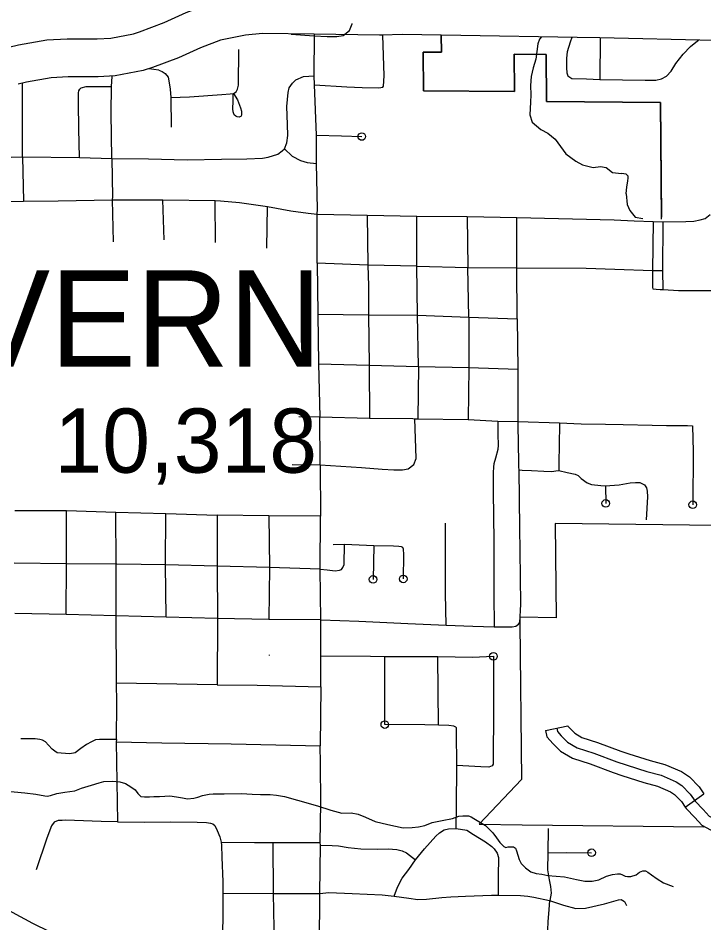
# Model space of a CAD drawing. Extents: x 22866 to 28196, y 1324810 to 1328105.
# Drawn here: x 25920.9 to 26029.2, y 1326074.4 to 1326217.3 of the extents above; entities that cross this region are included whole.
import ezdxf

# ---------------------------------------------------------------- set-up
doc = ezdxf.new("R2010")
doc.units = 0
for name, color, linetype in [('Level 15', 7, 'Continuous'), ('Level 32', 7, 'Continuous'), ('Level 33', 7, 'Continuous'), ('Level 34', 7, 'Continuous'), ('Level 35', 7, 'Continuous'), ('Level 45', 7, 'Continuous'), ('Level 6', 7, 'Continuous')]:
    doc.layers.add(name, color=color, linetype=linetype)

msp = doc.modelspace()

# ---------------------------------------------------------------- linework, layer by layer
at = {"layer": 'Level 15'}
for points in [[(25919.41, 1326212.66), (25920.94, 1326213.05), (25925.42, 1326213.84), (25928.65, 1326214), (25933.38, 1326214.01), (25935.53, 1326214.12), (25939.1, 1326214.79), (25940.06, 1326215.13), (25943.93, 1326216.56), (25947.41, 1326218.15), (25951.17, 1326219.57), (25955.89, 1326220.53), (25959.21, 1326220.87)], [(25959.47, 1326214.86), (25956.79, 1326214.59), (25952.84, 1326213.78), (25949.72, 1326212.6), (25946.22, 1326211.01), (25942.09, 1326209.48), (25940.65, 1326208.98), (25936.24, 1326208.14), (25933.54, 1326208.01), (25928.8, 1326208), (25926.09, 1326207.87), (25922.2, 1326207.18), (25920.88, 1326206.84)], [(26030.84, 1326213.73), (26012.77, 1326214.14), (26009.18, 1326214.22), (25990.8, 1326214.53), (25981.53, 1326214.67), (25978.42, 1326214.58), (25977.98, 1326214.59), (25967.67, 1326214.75), (25959.47, 1326214.86)]]:
    msp.add_lwpolyline(points, dxfattribs=at)
at = {"layer": 'Level 32'}
for points in [[(26005.96, 1326105.16), (26006.07, 1326104.63), (26006.69, 1326103.97), (26007.69, 1326102.97), (26009.21, 1326102.07), (26011.84, 1326101.22), (26015.48, 1326099.86), (26020.21, 1326098.31), (26022.46, 1326097.73)], [(26022.46, 1326097.73), (26024.82, 1326096.72), (26025.75, 1326096.1), (26027.05, 1326094.74), (26027.83, 1326093.66), (26029.11, 1326092.3), (26030.04, 1326091.29), (26030.97, 1326090.79), (26032.9, 1326090.24), (26034.92, 1326090.01), (26035.56, 1326089.96), (26040.41, 1326089.78), (26042.23, 1326089.85), (26045.53, 1326090.09), (26047.04, 1326090.24), (26047.74, 1326090.55), (26048.78, 1326091.17), (26050.29, 1326092.8), (26052.85, 1326094.47), (26054.83, 1326095.36), (26057.04, 1326095.67), (26058.39, 1326095.64)]]:
    msp.add_lwpolyline(points, dxfattribs=at)
at = {"layer": 'Level 33'}
for points in [[(25967.7, 1326206.72), (25967.64, 1326208.15), (25967.69, 1326214.75)], [(25967.7, 1326206.72), (25972.83, 1326206.41), (25975.23, 1326206.31), (25977.85, 1326206.25), (25978.5, 1326206.36), (25978.61, 1326206.54), (25978.71, 1326208.16), (25978.5, 1326214.58)], [(26008.33, 1326214.23), (26008.08, 1326213.48), (26007.64, 1326211.93), (26007.53, 1326210.97), (26007.53, 1326209.42), (26007.56, 1326208.64), (26007.72, 1326208.17), (26008.37, 1326207.72), (26010.67, 1326207.67), (26012.76, 1326207.57)], [(26012.82, 1326214.14), (26012.76, 1326207.57)], [(26019.95, 1326207.46), (26021.64, 1326207.49), (26022.5, 1326207.7), (26023.29, 1326208.09), (26024.02, 1326208.9), (26024.78, 1326210.1), (26025.93, 1326211.59), (26027.08, 1326212.77), (26027.94, 1326213.48)], [(26027.94, 1326213.48), (26028.38, 1326213.79)], [(25945, 1326204.75), (25947.95, 1326204.86), (25953.07, 1326205.22), (25954.38, 1326205.33), (25954.93, 1326205.38), (25955.32, 1326205.64), (25955.56, 1326206.03), (25955.69, 1326206.69), (25955.77, 1326212.31)], [(25943.09, 1326209.06), (25941.55, 1326209.28)], [(25943.09, 1326209.06), (25943.64, 1326208.86), (25944.09, 1326208.52), (25944.58, 1326207.94), (25944.69, 1326207.39), (25944.92, 1326206.03), (25945, 1326204.75), (25945.06, 1326200.04)], [(25935.66, 1326206.47), (25935.74, 1326208.05)], [(25963.46, 1326200.45), (25963.35, 1326203.33), (25963.54, 1326205.53), (25963.72, 1326206.26), (25964.22, 1326207.02), (25964.74, 1326207.52), (25965.97, 1326208.04), (25967.64, 1326208.15)], [(26012.76, 1326207.57), (26019.95, 1326207.46)], [(25921.57, 1326195.35), (25921.57, 1326207.06)], [(25930.56, 1326195.27), (25930.46, 1326199.8), (25930.43, 1326203.86), (25930.43, 1326205.48), (25930.46, 1326205.77), (25930.61, 1326206.08), (25930.82, 1326206.26), (25931.66, 1326206.45), (25935.66, 1326206.47)], [(25935.67, 1326195.13), (25935.57, 1326202.3), (25935.66, 1326206.47)], [(25968.01, 1326194.34), (25968.03, 1326195.43), (25968.01, 1326198.78), (25967.7, 1326206.72)], [(25954.93, 1326205.38), (25955.53, 1326204.35), (25956, 1326203.12), (25956.16, 1326202.57), (25956.18, 1326202), (25956.11, 1326201.81), (25955.82, 1326201.66), (25955.51, 1326201.71), (25955.27, 1326201.79), (25955.03, 1326202), (25954.85, 1326202.49), (25954.8, 1326202.94), (25954.83, 1326204.14), (25954.83, 1326205.37)], [(25935.67, 1326195.13), (25941.46, 1326195.05), (25947.57, 1326194.92), (25953.01, 1326195), (25957.03, 1326195.03), (25959.49, 1326195.16), (25960.4, 1326195.34), (25961.89, 1326195.81), (25962.6, 1326196.32), (25962.94, 1326196.63), (25963.35, 1326197.6), (25963.49, 1326198.75), (25963.46, 1326200.45)], [(25968.01, 1326198.78), (25971.98, 1326198.7), (25975.18, 1326198.58)], [(25962.94, 1326196.63), (25964.2, 1326195.5), (25965.47, 1326194.77), (25966.55, 1326194.48), (25968.01, 1326194.34)], [(25881.98, 1326194.77), (25890.11, 1326194.85), (25906.86, 1326195.09), (25912.56, 1326195.11), (25921.57, 1326195.35), (25930.56, 1326195.27), (25935.67, 1326195.13)], [(25921.57, 1326195.35), (25921.73, 1326188.38)], [(25935.67, 1326195.13), (25935.77, 1326189.06), (25935.76, 1326188.59)], [(25968.14, 1326186.31), (25968.17, 1326187.12), (25968.01, 1326194.34)], [(25907.72, 1326187.93), (25912.56, 1326188.17), (25915.81, 1326188.27), (25921.73, 1326188.38), (25927.23, 1326188.45), (25935.76, 1326188.59)], [(25935.76, 1326188.59), (25943.77, 1326188.59)], [(25935.76, 1326188.59), (25935.92, 1326181.97)], [(25943.77, 1326188.59), (25952, 1326188.48), (25952.86, 1326188.44), (25955.83, 1326188.15), (25960.26, 1326187.51), (25963.98, 1326186.82), (25966.7, 1326186.46), (25968.14, 1326186.31), (25970.76, 1326186.25), (25976.02, 1326186.16), (25983.87, 1326186.02), (25991.82, 1326185.97), (25999.66, 1326185.78), (26015.05, 1326185.41), (26018.2, 1326185.28), (26021.2, 1326185.17), (26022.79, 1326185.13), (26026.35, 1326185.15), (26027.6, 1326185.19), (26028.63, 1326185.4), (26029.42, 1326185.66), (26030.18, 1326186.27)], [(25943.96, 1326182.25), (25943.77, 1326188.59)], [(25952.09, 1326181.83), (25952, 1326188.48)], [(25960.15, 1326180.96), (25960.26, 1326187.51)], [(25968.15, 1326178.6), (25968.14, 1326186.31)], [(25976.02, 1326186.16), (25976.15, 1326178.25), (25976.22, 1326175), (25976.22, 1326170.41)], [(25983.85, 1326178.11), (25983.87, 1326186.02)], [(25991.82, 1326185.97), (25991.92, 1326177.92)], [(25999.69, 1326177.85), (25999.66, 1326185.78)], [(26021.2, 1326185.17), (26021.12, 1326177.44)], [(26022.78, 1326174.43), (26022.74, 1326177.41), (26022.79, 1326185.13)], [(25968.15, 1326178.6), (25968.22, 1326170.52)], [(25976.15, 1326178.25), (25968.15, 1326178.6)], [(25983.85, 1326178.11), (25976.15, 1326178.25)], [(25983.98, 1326170.36), (25983.85, 1326178.11), (25991.92, 1326177.92)], [(25992.07, 1326170.06), (25991.92, 1326177.92)], [(25991.92, 1326177.92), (25999.69, 1326177.85)], [(25999.72, 1326169.79), (25999.69, 1326177.85)], [(25999.69, 1326177.85), (26010.6, 1326177.77), (26015.17, 1326177.66), (26021.12, 1326177.44)], [(26021.12, 1326177.44), (26021.07, 1326175.38), (26021.08, 1326174.75), (26021.14, 1326174.54), (26021.65, 1326174.47), (26022.3, 1326174.43), (26022.78, 1326174.43), (26025.21, 1326174.25), (26029.09, 1326174.25), (26030.8, 1326174.27)], [(26021.12, 1326177.44), (26022.74, 1326177.41)], [(25968.22, 1326170.52), (25976.22, 1326170.41), (25983.98, 1326170.36), (25992.07, 1326170.06), (25999.72, 1326169.79)], [(25968.22, 1326170.52), (25968.33, 1326162.69)], [(25976.22, 1326170.41), (25976.35, 1326162.46), (25976.41, 1326154.1)], [(25984.14, 1326162.26), (25983.98, 1326170.36)], [(25992.07, 1326170.06), (25992.06, 1326162.09)], [(25999.72, 1326169.79), (25999.83, 1326161.84)], [(25968.33, 1326162.69), (25968.56, 1326154.33)], [(25968.33, 1326162.69), (25976.35, 1326162.46), (25984.14, 1326162.26), (25992.06, 1326162.09), (25999.83, 1326161.84)], [(25984.14, 1326162.26), (25984, 1326154.02)], [(25992.06, 1326162.09), (25992, 1326153.89)], [(25999.83, 1326161.84), (25999.84, 1326153.56)], [(25965.23, 1326154.39), (25968.56, 1326154.33), (25976.41, 1326154.1), (25983.22, 1326154.06), (25983.57, 1326154.03), (25984, 1326154.02), (25992, 1326153.89), (25996.68, 1326153.66)], [(25968.59, 1326146.75), (25968.56, 1326154.33)], [(25983.77, 1326147.8), (25983.57, 1326154.03)], [(25996.68, 1326153.66), (25996.66, 1326151.52), (25996.73, 1326149.85), (25996.64, 1326149.18), (25996.31, 1326147.81), (25996.02, 1326146.9), (25995.97, 1326146.45), (25995.93, 1326145.47), (25995.95, 1326142.54), (25996.04, 1326134.71), (25996.02, 1326130.88), (25996.04, 1326126.34), (25996.08, 1326121.15)], [(25996.68, 1326153.66), (25999.84, 1326153.56), (26006.38, 1326153.35)], [(25999.84, 1326153.56), (25999.83, 1326152.29), (25999.88, 1326150.83), (25999.94, 1326146.38), (25999.97, 1326145.96), (26000.5, 1326145.88), (26001.98, 1326145.84), (26003.92, 1326145.75), (26005.19, 1326145.7), (26005.82, 1326145.81), (26006.3, 1326145.86)], [(26006.38, 1326153.35), (26006.36, 1326149.7), (26006.31, 1326147.27), (26006.3, 1326145.86)], [(26006.38, 1326153.35), (26009.84, 1326153.24), (26013.67, 1326153.14), (26016.44, 1326153.09), (26021.05, 1326152.99), (26023.28, 1326152.95), (26026.62, 1326152.94), (26027.43, 1326152.91), (26027.53, 1326148.86), (26027.45, 1326140.45)], [(25968.59, 1326146.75), (25968.63, 1326138.63), (25960.5, 1326138.71), (25952.32, 1326138.79)], [(25964.15, 1326146.78), (25968.59, 1326146.75)], [(25968.59, 1326146.75), (25975.12, 1326146.31)], [(25999.97, 1326145.96), (26000.1, 1326136.73), (26000.15, 1326133.15), (26000.23, 1326124.75), (26000.1, 1326121.8)], [(26006.3, 1326145.86), (26007.6, 1326145.52), (26008.89, 1326145.28), (26009.34, 1326145.08), (26009.81, 1326144.61), (26010.75, 1326143.91), (26011.44, 1326143.62), (26012.94, 1326143.49), (26013.65, 1326143.44)], [(26013.65, 1326143.44), (26014.34, 1326143.47), (26015.84, 1326143.58), (26017.58, 1326143.91), (26018.43, 1326143.98), (26019.08, 1326143.94), (26019.82, 1326143.56), (26020.15, 1326143.11), (26020.24, 1326142.59), (26020.28, 1326141.7), (26020.11, 1326138.06)], [(26013.65, 1326143.44), (26013.7, 1326140.65)], [(25920.39, 1326139.55), (25928.1, 1326139.53), (25928.53, 1326139.52)], [(25928.53, 1326131.13), (25928.53, 1326139.52)], [(25928.53, 1326139.52), (25936.31, 1326139.29), (25944.22, 1326139.06)], [(25936.41, 1326112.3), (25936.4, 1326122.88), (25936.4, 1326131.07), (25936.31, 1326139.29)], [(25944.27, 1326122.67), (25944.16, 1326130.96), (25944.22, 1326139.06)], [(25944.22, 1326139.06), (25952.32, 1326138.79)], [(25952.32, 1326138.79), (25952.33, 1326130.74), (25952.37, 1326122.5), (25952.32, 1326112.03)], [(25960.5, 1326138.71), (25960.57, 1326130.56), (25960.51, 1326122.31)], [(25968.73, 1326111.7), (25968.7, 1326116.61), (25968.7, 1326122.26), (25968.62, 1326130.29), (25968.63, 1326138.63)], [(25988.48, 1326121.44), (25988.4, 1326126.41), (25988.4, 1326137.52)], [(25968.62, 1326130.29), (25969.69, 1326130.14), (25970.96, 1326130.03), (25971.66, 1326130.12), (25971.99, 1326130.23), (25972.19, 1326130.56), (25972.39, 1326131.03), (25972.42, 1326134.21)], [(25970.63, 1326134.19), (25972.42, 1326134.21), (25977.09, 1326134.01), (25980.19, 1326133.94), (25981.02, 1326133.92), (25981.38, 1326133.83), (25981.58, 1326133.72), (25981.73, 1326133.47), (25981.76, 1326132.51), (25981.73, 1326128.73)], [(25977.09, 1326134.01), (25976.95, 1326128.66)], [(25968.62, 1326130.29), (25960.57, 1326130.56), (25952.33, 1326130.74), (25944.16, 1326130.96), (25936.5, 1326131.05), (25928.53, 1326131.13), (25920.28, 1326131.23)], [(25928.48, 1326123.1), (25928.53, 1326131.13)], [(25936.4, 1326122.88), (25928.48, 1326123.1), (25920.38, 1326123.26)], [(25952.37, 1326122.5), (25944.27, 1326122.67), (25936.4, 1326122.88)], [(25968.7, 1326122.26), (25960.51, 1326122.31), (25952.37, 1326122.5)], [(25968.7, 1326122.26), (25974.73, 1326122.04), (25982.45, 1326121.68), (25988.48, 1326121.44), (25992.74, 1326121.29), (25996.08, 1326121.15), (25997.86, 1326121.15), (25998.91, 1326121.15), (25999.48, 1326121.29), (25999.93, 1326121.59), (26000.1, 1326121.8)], [(25968.7, 1326116.61), (25976.54, 1326116.51), (25978.81, 1326116.48), (25987.18, 1326116.46), (25992.64, 1326116.4), (25995.96, 1326116.51), (25995.96, 1326111.73), (25995.96, 1326107.67), (25995.93, 1326100.37), (25995.93, 1326099.8), (25995.9, 1326099.46), (25995.77, 1326099.2), (25995.23, 1326099.02), (25993.97, 1326099.07), (25990.17, 1326099.26)], [(25978.81, 1326105.73), (25978.81, 1326116.48)], [(25987.31, 1326105.66), (25987.18, 1326116.46)], [(25936.41, 1326103.36), (25936.46, 1326109.16), (25936.41, 1326112.3), (25952.31, 1326112.05)], [(25952.32, 1326112.03), (25958.64, 1326111.96), (25968.73, 1326111.7)], [(25968.73, 1326111.7), (25968.59, 1326102.4)], [(25990.09, 1326089.33), (25990.12, 1326092.7), (25990.17, 1326099.26), (25990.16, 1326104.52), (25990.15, 1326105.2), (25990.04, 1326105.32), (25989.69, 1326105.49), (25988.93, 1326105.61), (25987.31, 1326105.66), (25985.11, 1326105.67), (25978.81, 1326105.73)], [(25936.41, 1326103.36), (25934.84, 1326103.38), (25933.74, 1326103.36), (25933.09, 1326103.3), (25932.48, 1326103.02), (25931.67, 1326102.6), (25930.81, 1326101.94), (25929.92, 1326101.26), (25929.06, 1326101.14), (25927.7, 1326101.24), (25927.05, 1326101.29), (25926.66, 1326101.52), (25926.29, 1326101.86), (25925.66, 1326102.49), (25925.19, 1326102.99), (25924.72, 1326103.28), (25924.3, 1326103.36), (25923.57, 1326103.46), (25921.32, 1326103.49)], [(25936.41, 1326103.36), (25936.4, 1326103.02), (25936.56, 1326090.36)], [(25936.4, 1326103.02), (25943.59, 1326102.84), (25954.54, 1326102.68), (25966.3, 1326102.42), (25968.59, 1326102.4)], [(25968.55, 1326079.07), (25968.63, 1326086.68), (25968.6, 1326087.1), (25968.71, 1326093.31), (25968.65, 1326099.64), (25968.59, 1326102.4)], [(25936.56, 1326090.36), (25933.98, 1326090.42), (25929.8, 1326090.58), (25928.42, 1326090.63), (25927.82, 1326090.61), (25927.19, 1326090.58), (25926.56, 1326090.32), (25926.14, 1326089.77), (25925.41, 1326087.81), (25923.74, 1326082.81)], [(25936.56, 1326090.36), (25940.84, 1326090.34), (25944.92, 1326090.37), (25949.16, 1326090.34), (25950.62, 1326090.27), (25951.27, 1326090.19), (25951.67, 1326090.06), (25951.95, 1326089.79), (25952.34, 1326089.02), (25952.74, 1326087.99), (25952.97, 1326087.18), (25953, 1326086.69), (25953.05, 1326084.8), (25953.2, 1326080.93), (25953.23, 1326079.12)], [(25980.28, 1326078.65), (25980.8, 1326080.04), (25981.56, 1326081.47), (25982.58, 1326082.83), (25983.68, 1326084.4), (25985.09, 1326086.11), (25986.89, 1326088.11), (25987.44, 1326088.64), (25988.19, 1326089.13), (25988.85, 1326089.29), (25990.09, 1326089.33)], [(25990.09, 1326089.33), (25991.75, 1326089.06), (25992.82, 1326088.38), (25994.7, 1326087.2), (25995.69, 1326086.47), (25996.11, 1326086.13), (25996.58, 1326085.42), (25996.77, 1326084.77), (25996.69, 1326081.76), (25996.74, 1326078.78)], [(26004.91, 1326077.95), (26005.13, 1326079.12), (26005.06, 1326080.18), (26004.85, 1326081.24), (26004.54, 1326082.82), (26004.61, 1326085.51), (26004.68, 1326089.34)], [(25952.97, 1326087.18), (25958.25, 1326087.12), (25961.18, 1326087.09)], [(25961.18, 1326087.09), (25963.71, 1326087.09), (25968.6, 1326087.1)], [(25961.21, 1326079.04), (25961.18, 1326087.09)], [(25968.63, 1326086.68), (25970.47, 1326086.65), (25971.47, 1326086.58), (25973.01, 1326086.34), (25975.02, 1326086.11), (25977.61, 1326086.05), (25979.34, 1326086.11), (25980.72, 1326086), (25981.53, 1326085.79), (25982.26, 1326085.48), (25983.68, 1326084.4)], [(26004.61, 1326085.51), (26007.53, 1326085.52), (26011.47, 1326085.49)], [(25953.2, 1326070.87), (25945.13, 1326070.88), (25938.31, 1326070.9), (25936.09, 1326070.95), (25932.09, 1326071.31), (25928.56, 1326071.94), (25927.7, 1326072.15), (25925.88, 1326073.01), (25923.23, 1326074.32), (25919.98, 1326076.04), (25918.96, 1326076.57), (25916.5, 1326078), (25912.93, 1326080.21), (25910.68, 1326081.61)], [(25953.23, 1326079.12), (25953.23, 1326075.5), (25953.15, 1326072.91), (25953.2, 1326070.87)], [(25953.23, 1326079.12), (25961.21, 1326079.04), (25968.55, 1326079.07), (25969.95, 1326079.2), (25973.64, 1326079.07), (25978.4, 1326078.83), (25980.28, 1326078.65), (25982.58, 1326078.33), (25984.02, 1326078.13), (25985.38, 1326078.15), (25987.83, 1326078.41), (25989.26, 1326078.54), (25991.54, 1326078.62), (25995.67, 1326078.78), (25996.74, 1326078.78), (26000.22, 1326078.75), (26001.39, 1326078.65), (26002.36, 1326078.49), (26004.84, 1326077.97)], [(25961.4, 1326070.88), (25961.21, 1326079.04)], [(25968.51, 1326070.79), (25968.55, 1326079.07)], [(26004.84, 1326077.97), (26004.7, 1326076.55), (26004.56, 1326074.6), (26004.53, 1326073.33), (26004.49, 1326072.3), (26004.66, 1326071.48), (26005.45, 1326070.14), (26007.27, 1326068.63), (26008.57, 1326067.43), (26008.81, 1326067.11), (26009.22, 1326066.11), (26009.46, 1326065.32), (26009.43, 1326064.26), (26009.22, 1326062.65), (26009.15, 1326061.75), (26008.33, 1326058.46)], [(26004.84, 1326077.97), (26007.01, 1326077.24), (26009, 1326076.69), (26010.51, 1326076.73), (26013.52, 1326077.45), (26015.72, 1326078.06), (26016.16, 1326078.1), (26016.68, 1326077.82), (26016.99, 1326077.17)]]:
    msp.add_lwpolyline(points, dxfattribs=at)
for centre in [(25975.18, 1326198.58), (26013.7, 1326140.65), (26027.45, 1326140.45), (25976.95, 1326128.66), (25981.73, 1326128.73), (25995.96, 1326116.51), (25978.81, 1326105.73), (26011.47, 1326085.49)]:
    msp.add_circle(centre, 0.6, dxfattribs=at)
at = {"layer": 'Level 34'}
for points in [[(25964, 1326214.75), (25967.64, 1326214.45), (25969.69, 1326214.35), (25971.24, 1326214.35), (25972.24, 1326214.55), (25973.24, 1326215.3), (25973.66, 1326216.35), (25973.66, 1326216.43)], [(25975.12, 1326146.31), (25978.38, 1326146.04), (25980.21, 1326145.95), (25981.6, 1326145.95), (25982.49, 1326146.13), (25983.39, 1326146.8), (25983.77, 1326147.74), (25983.77, 1326147.8)], [(25960.55, 1326116.74), (25960.56, 1326116.62)]]:
    msp.add_lwpolyline(points, dxfattribs=at)
at = {"layer": 'Level 35'}
for points in [[(26003.57, 1326214.31), (26003.22, 1326213.93), (26002.98, 1326213.22), (26002.67, 1326210.78), (26002.24, 1326209.4), (26001.92, 1326208.07), (26001.84, 1326206.65), (26001.88, 1326205.15), (26001.8, 1326204.01)], [(26001.8, 1326204.01), (26001.72, 1326201.98), (26002.08, 1326200.87), (26003.46, 1326199.69), (26004.56, 1326199.1), (26005.74, 1326198.16), (26007.43, 1326195.87), (26009.01, 1326194.71), (26010.03, 1326194.12), (26011.72, 1326193.69), (26012.86, 1326193.85), (26013.76, 1326193.69), (26014.79, 1326192.9), (26016.2, 1326192.74)], [(26016.95, 1326189.51), (26017.03, 1326190.62), (26017.19, 1326191.52), (26017.26, 1326192.03), (26017.26, 1326192.31), (26016.91, 1326192.62), (26016.2, 1326192.74)], [(26016.95, 1326189.51), (26017.11, 1326187.86), (26017.54, 1326186.88), (26018.37, 1326185.85), (26019.55, 1326185.65)], [(25919.15, 1326095.21), (25921.95, 1326094.97), (25923.68, 1326094.76), (25925.08, 1326094.48), (25925.45, 1326094.45), (25926, 1326094.53), (25926.99, 1326094.87), (25927.64, 1326094.95), (25928.24, 1326095.08), (25929.03, 1326095.19), (25929.84, 1326095.29), (25930.88, 1326095.71), (25932.5, 1326096.16), (25933.71, 1326096.55), (25934.44, 1326096.76), (25935.74, 1326096.81), (25936.97, 1326096.68), (25937.86, 1326096.42), (25938.69, 1326095.89), (25939.35, 1326095.42), (25939.79, 1326094.85), (25940.26, 1326094.4), (25940.84, 1326094.35), (25941.65, 1326094.35), (25942.35, 1326094.38), (25943.24, 1326094.4), (25944.08, 1326094.45), (25944.84, 1326094.51), (25945.88, 1326094.35), (25946.87, 1326094.17), (25947.63, 1326094.01), (25948.63, 1326094.09), (25949.25, 1326094.25), (25950.01, 1326094.56), (25951.08, 1326094.77), (25951.68, 1326094.82), (25953.44, 1326094.82), (25956.15, 1326094.85), (25957.85, 1326094.77), (25959.16, 1326094.72), (25960.68, 1326094.69), (25961.72, 1326094.59), (25962.99, 1326094.36), (25965, 1326093.79), (25968.19, 1326092.9)], [(25968.19, 1326092.9), (25970.26, 1326092.22), (25972.01, 1326091.74), (25973.47, 1326091.8), (25974.59, 1326091.59), (25975.74, 1326091.09), (25977.31, 1326090.44), (25979.27, 1326089.94), (25981.7, 1326089.42), (25983.14, 1326089.47), (25984.11, 1326089.57), (25985.13, 1326089.81), (25986.3, 1326090.28), (25987.87, 1326090.59), (25989.49, 1326090.91)], [(25989.49, 1326090.91), (25990.5, 1326091.27), (25991.13, 1326091.3), (25992.02, 1326091.3), (25992.44, 1326091.19), (25992.88, 1326090.88), (25994.69, 1326089.78), (25995.89, 1326088.63), (25996.46, 1326087.85), (25996.99, 1326087.09), (25997.61, 1326086.46), (25997.93, 1326086.33), (25998.29, 1326086.41), (25998.66, 1326086.41), (25999.16, 1326086.41), (25999.44, 1326086.2), (25999.6, 1326085.78), (26000.02, 1326084.44), (26000.33, 1326083.8), (26001.03, 1326083.12), (26001.87, 1326082.51), (26002.73, 1326082.2), (26003.62, 1326082.12), (26004.54, 1326081.91), (26005.87, 1326081.81), (26007.2, 1326081.68), (26009.11, 1326081.28), (26010.42, 1326081), (26011.57, 1326081.02), (26012.61, 1326081.21), (26013.81, 1326081.78), (26014.76, 1326082.04), (26015.57, 1326082.17), (26016.01, 1326082.15), (26016.34, 1326082), (26016.79, 1326081.79), (26017.13, 1326081.76), (26017.65, 1326081.76), (26018.49, 1326082), (26019.06, 1326082.42), (26019.56, 1326082.63), (26019.98, 1326082.65), (26020.37, 1326082.42), (26020.95, 1326082), (26021.83, 1326081.37), (26022.83, 1326080.77), (26024.37, 1326080.17)]]:
    msp.add_lwpolyline(points, dxfattribs=at)
at = {"layer": 'Level 45'}
for p, q in [((26004.2, 1326104.81), (26007.73, 1326105.51)), ((26026.28, 1326092.72), (26029.22, 1326094.81))]:
    msp.add_line(p, q, dxfattribs=at)
for points in [[(26004.2, 1326104.81), (26004.4, 1326103.78), (26005.39, 1326102.72), (26006.58, 1326101.53), (26008.46, 1326100.42), (26011.25, 1326099.52), (26014.89, 1326098.16), (26016.25, 1326097.72)], [(26007.73, 1326105.51), (26007.73, 1326105.49), (26007.98, 1326105.23), (26008.81, 1326104.4), (26009.95, 1326103.72), (26012.43, 1326102.92), (26016.08, 1326101.56), (26017.37, 1326101.14)], [(26017.37, 1326101.14), (26020.72, 1326100.04), (26023.04, 1326099.44), (26025.68, 1326098.31), (26026.92, 1326097.49), (26028.44, 1326095.89), (26029.22, 1326094.81)], [(26016.25, 1326097.72), (26019.7, 1326096.58), (26021.88, 1326096.02), (26023.96, 1326095.13), (26024.59, 1326094.71), (26025.66, 1326093.59), (26026.28, 1326092.72)], [(26026.28, 1326092.72), (26026.43, 1326092.51), (26027.79, 1326091.07), (26028.91, 1326089.85), (26030.28, 1326089.11), (26032.55, 1326088.47), (26034.75, 1326088.22), (26035.46, 1326088.16), (26039.05, 1326088.03)]]:
    msp.add_lwpolyline(points, dxfattribs=at)
at = {"layer": 'Level 6'}
for points in [[(26022.54, 1326185.55), (26022.36, 1326203.97), (26004.37, 1326204.1), (26004.3, 1326211.54), (25999.26, 1326211.58), (25999.31, 1326205.7), (25984.91, 1326205.8), (25984.86, 1326211.92), (25987.74, 1326211.9), (25987.71, 1326214.58)], [(25987.71, 1326214.56), (25987.74, 1326211.9), (25984.86, 1326211.92)], [(25984.86, 1326211.92), (25984.91, 1326205.8), (25999.31, 1326205.7), (25999.26, 1326211.58), (26004.3, 1326211.54), (26004.37, 1326204.1), (26022.36, 1326203.97), (26022.53, 1326185.82)], [(26030.71, 1326187.77), (26030.72, 1326186.78), (26030.73, 1326185.03), (26040.81, 1326184.89), (26040.91, 1326174.8), (26030.84, 1326174.94), (26031.07, 1326153), (26031.2, 1326137.14), (26005.74, 1326137.47), (26005.9, 1326122.59), (26000.14, 1326122.67), (26000.15, 1326121.68), (26000.42, 1326097.07), (25993.74, 1326090.02), (26000.49, 1326089.93), (26029.18, 1326089.57)]]:
    msp.add_lwpolyline(points, dxfattribs=at)

# ---------------------------------------------------------------- texts
for s, height, p in [('MALVERN', 15.209, (25870.55, 1326162.24)), ('10,318', 10.139, (25926.63, 1326145.5))]:
    msp.add_text(s, height=height, dxfattribs=at).set_placement(p)

doc.saveas('drawing.dxf')
